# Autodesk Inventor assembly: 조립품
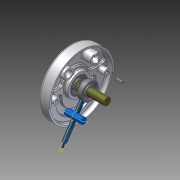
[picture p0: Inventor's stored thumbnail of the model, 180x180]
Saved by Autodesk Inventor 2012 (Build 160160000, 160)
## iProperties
Created: 2015-04
Part Number: 조립품
Document SubType Name: Assembly
Designer: Owner
Author: Owner
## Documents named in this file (8)
- C:\Documents and Settings\Owner\바탕 화면\450405V1008\조립품.iam
- C:\Documents and Settings\Owner\바탕 화면\450405V1008\문제보기2.ipt
- C:\Documents and Settings\Owner\바탕 화면\450405V1008\덮개.ipt
- C:\Documents and Settings\Owner\바탕 화면\450405V1008\베어링62_22.ipt
- C:\Documents and Settings\Owner\바탕 화면\450405V1008\축.ipt
- C:\Documents and Settings\Owner\바탕 화면\450405V1008\평행핀.ipt
- C:\Documents and Settings\Owner\바탕 화면\450405V1008\슬라이더.ipt
- C:\Documents and Settings\Owner\바탕 화면\450405V1008\슬라이더2.ipt
